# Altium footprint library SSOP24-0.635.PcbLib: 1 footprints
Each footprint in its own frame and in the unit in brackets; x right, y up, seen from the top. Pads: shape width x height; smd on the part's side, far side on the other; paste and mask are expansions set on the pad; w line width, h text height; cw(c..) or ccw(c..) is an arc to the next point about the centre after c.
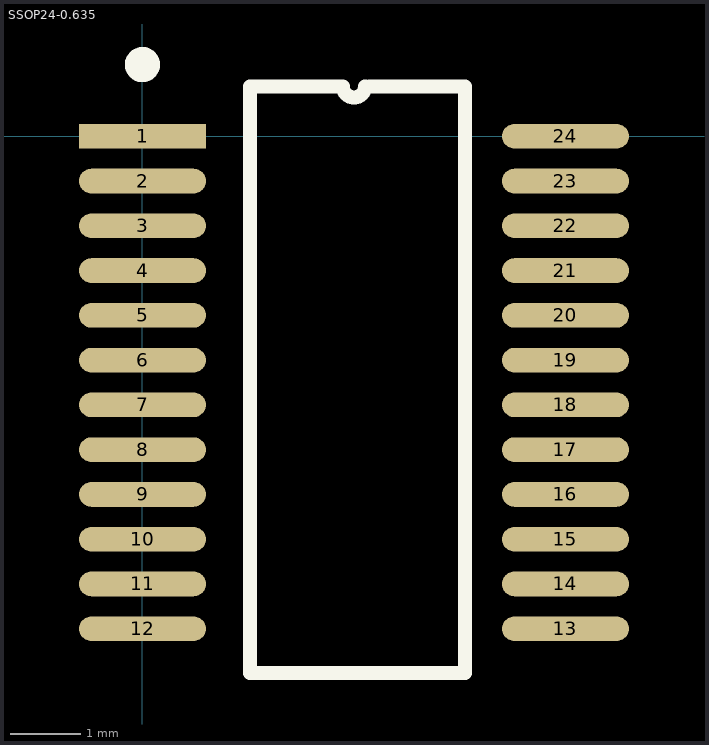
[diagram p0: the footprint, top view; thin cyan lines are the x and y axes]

## SSOP24-0.635 [mm]
pads (24):
  rect 1.8x0.35 smd: 1(0,0)
  oval 1.8x0.35 smd: 2(0,-0.635) 3(0,-1.27) 4(0,-1.905) 5(0,-2.54) 6(0,-3.175) 7(0,-3.81) 8(0,-4.445) 9(0,-5.08) 10(0,-5.715) 11(0,-6.35) 12(0,-6.985) 13(6,-6.985) 14(6,-6.35) 15(6,-5.715) 16(6,-5.08) 17(6,-4.445) 18(6,-3.81) 19(6,-3.175) 20(6,-2.54) 21(6,-1.905) 22(6,-1.27) 23(6,-0.635) 24(6,0)
Top Overlay:
  circle w0.25: c0,1.016 r0.125
  lines w0.2: 3.159,0.708 cw(c3,0.708) 2.841,0.708 1.524,0.708 1.524,-7.61 4.572,-7.61 4.572,0.708 3.223,0.708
